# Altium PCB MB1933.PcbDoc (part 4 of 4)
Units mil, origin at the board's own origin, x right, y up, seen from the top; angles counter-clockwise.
Board outline 2755.91 x 3937.01 mil, 4 copper layers (Top Layer, GND, POWER, Bottom Layer), stack 60.63 mil thick; 228 components, 185 nets, 918 pads, 786 vias.
Unrouted connection lines stored in the file: 160.
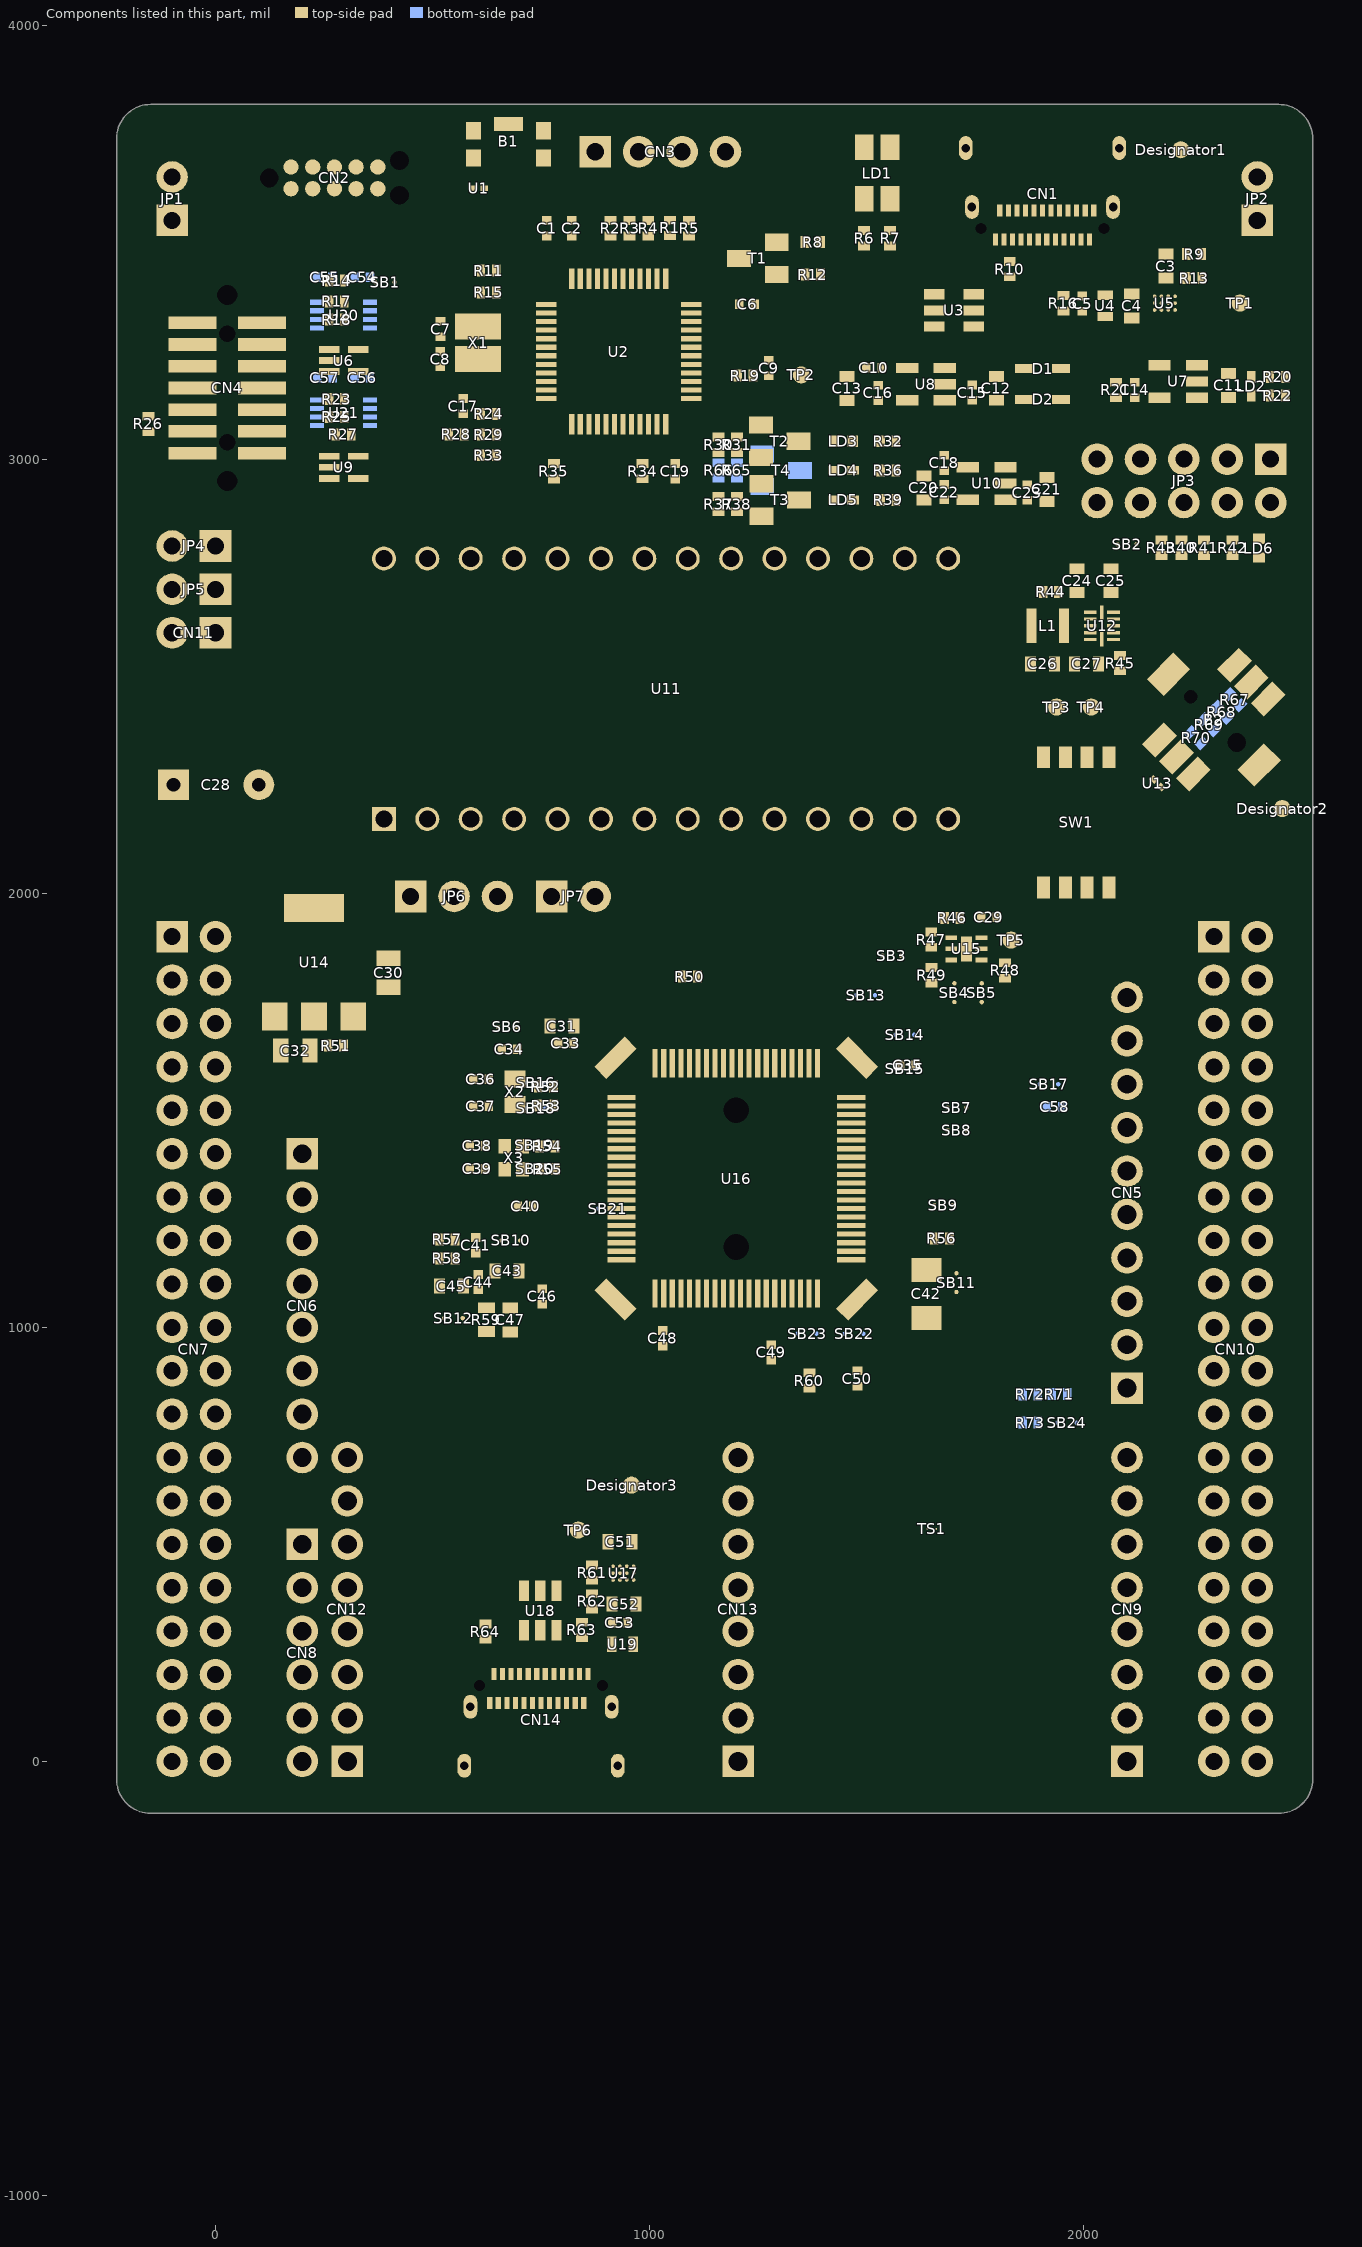
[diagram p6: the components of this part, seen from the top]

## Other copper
Top Layer:
  pour cut-out: 792.82,1551.81 ccw(c808.57,1551.81) 808.57,1536.06 ccw(c808.57,1551.81) 824.32,1551.81 ccw(c808.57,1551.81) 808.57,1567.56 ccw(c808.57,1551.81)
  region net 3V3: 1838,2694.28 1821.28,2711 1818,2711 1816,2709 1816,2673 1837.28,2694.28
  region net AVDD: 711,1057 680,1057 678,1055 687.79,1045.21 707.99,1045.21 710.78,1048
  pour cut-out: 779,3245 744.97,3245 659.97,3160 508.05,3160 485,3183.05 485,3339 504,3358 674,3358 741,3291 797,3291 797,3312 750,3312 684,3378 486,3378 464,3356 464,3160 486,3138 665.91,3138 742.91,3215 796,3215 797,3216 797,3245
  pour cut-out: 716.57,1618.17 625.41,1618.17 613.29,1630.29 621,1638 710.98,1638 716.57,1632.41
  region net VBUS2: 793.01,217.04 793.01,226.01 812.08,245.08 875.79,245.08 901.77,271.06 901.57,368.41 924.7,368.41 926.57,366.54 926.48,254.43 896.75,224.7 812.7,224.7 798.93,210.93
  region net 5V_USB: 927.46,443.68 927.46,467.03 947.05,486.61 947.05,507.68 965.26,507.68 972.05,500.89 972.05,478.94 951.77,458.66 951.77,451.67 948.13,448.03
  region net 5V_USB: 931.59,434.84 945.08,448.33 931.59,448.33
  region net VBUS2: 946,434.04 951.77,428.27 951.77,400 923.77,372 901.28,372 901.28,384.28 930,413 930,416 933,416 946,429
  region net VBUS2: 947.52,432.52 933,418 947.52,418
  region net GND: 1717.47,3196.82 1717.47,3181.75 1720.96,3178.25 1764.61,3178.25 1771.44,3185.09 1771.44,3193.47
  pour cut-out: 584.06,1549.03 584.06,1468.05 533.65,1468.05 533.65,1551.27
  pour cut-out: 559.36,1459.94 562.02,1459.94 562.02,1436.36 534.16,1436.36 534.16,1461.06
  pour cut-out: 561.03,1472.97 817.33,1472.97 817.33,1459.49 505.48,1459.49 505.48,1472.58
  pour cut-out: 538.69,1351.12 538.69,1287.34 543.02,1283.01 562.01,1283.01 565.7,1286.69 565.7,1354.62 561.52,1358.8 543.26,1358.8 541.54,1357.08
  region net VDD_MCU: 902.68,1503.97 892.73,1503.97 876.88,1519.82 876.88,1536.34 897.53,1515.69 903.53,1515.69 905.96,1513.25 905.96,1507.25
  region net VBUS: 1954.49,3495.33 1965.95,3483.87 1965.95,3435.27 2015.66,3385.57 2015.66,3379.66 1995.87,3379.66 1954.49,3421.05
  pour cut-out: 251.09,3522.13 251.09,3416.13 192.63,3416.13 188.1,3420.66
  pour cut-out: 289.13,3456.04 183.13,3456.04 183.13,3514.51 187.65,3519.03
  pour cut-out: 370.28,3494.92 339.77,3494.92 328.85,3505.84 328.85,3517.66 346.07,3534.88 347.35,3533.6 369.79,3533.6
  region net GND: 2110.2,3387.07 2137.17,3387.07 2144.95,3379.3 2144.95,3368.18 2117.19,3368.18 2109.91,3375.46 2109.91,3386.58
  region net GND: 2163.55,3375.25 2163.55,3343.76 2142.4,3343.76 2133.57,3352.58 2133.57,3375.25
  pour cut-out: 1926.42,3196.1 1926.42,3147.97 1933.61,3140.79 1937.74,3144.92 1997.59,3144.92 2006.44,3153.78 2006.44,3191.77 2003.98,3194.23
  pour cut-out: 1856.7,2453.48 1825.6,2453.48 1816.54,2462.54 1816.54,2508.31 1824.52,2516.28 1859.95,2516.28 1873.04,2502.89 1873.04,2459.19 1867.82,2453.97
  pour cut-out: 1944.69,2577.4 1894.2,2577.4 1888.39,2583.21 1890.56,2585.37 1890.56,2695.9 1848.43,2695.9 1830.55,2678.02 1830.55,2586.13 1846.27,2570.41 1868.71,2570.41
  pour cut-out: 901.08,1542.17 901.08,1576.62 891.65,1586.05 869.91,1564.31 859.86,1564.31 859.86,1526.94 870.49,1516.31
  region net VDD_MCU: 1346.66,1046.1 1341.74,1041.18 1341.74,1030.16 1269.59,958.01 1269.59,950 1290.52,950 1315.76,975.23 1353.45,1012.93 1353.45,1046.1
  region net GND: 1601.68,1615 1601.68,1595.67 1521.7,1515.69 1519.79,1515.69 1513.49,1509.39 1518.9,1503.97 1540.97,1503.97 1623,1586 1623,1615
  pour cut-out: 306.6,1795.51 247.25,1795.51 236.23,1784.49 236.23,1709.68 248.43,1697.48 297.94,1697.48 316.64,1716.18 316.64,1785.47
  region net 3V3_STLK: 808.91,3199.1 815.07,3192.95 831.8,3192.95 848.43,3209.58 848.43,3232.71 842.53,3232.71
  region net 3V3_STLK: 1114.97,3355.06 1126.88,3366.97 1197.18,3366.97 1206.73,3357.42 1206.73,3355.06
  region net VDDUSB: 1477.62,1534.09 1479,1535.47 1496.66,1535.47 1562.07,1600.88 1562.07,1621.79 1586.68,1621.79 1586.68,1597.1 1513.23,1523.66 1477.62,1523.66
  region net VDD: 2064.64,2596.32 2085.82,2596.32 2091.74,2590.39 2091.74,2545.98 2096.86,2540.86 2119,2563 2119,2586.56 2101.39,2604.17 2072.49,2604.17
  region net GND: 2008.18,2604.17 1993.22,2604.17 1975.18,2586.14 1975.18,2545.25 1991.96,2545.25 1994.2,2547.49 1994.2,2590.69 1999.91,2596.4 2011.57,2596.4 2015.43,2600.25
  region net NetL1_1: 2015.43,2616 2011.51,2619.92 1990.95,2619.92 1965.87,2645 1958.34,2645 1958.34,2584.27 1986.12,2612.04 2015.47,2612.04
  region net 5V_LP: 2037.96,2705.25 2036.23,2703.52 2036.23,2660.18 2047.84,2660.18 2074.24,2686.58 2055.57,2705.25
  region net 5V_LP: 2000.7,2637.54 2032.78,2637.54 2036.23,2640.98 2036.23,2688.51 2042,2694.28 2047.84,2694.28 2047.84,2631.73 2043.12,2627.01 2000.7,2627.01
  region net 3V3_STLK: 810.24,3508.4 810.24,3445.71 818.22,3437.73 825.01,3437.83 825.01,3513.13 823.85,3514.28 816.12,3514.28
  region net 3V3_STLK: 1038,3059.19 1046.56,3050.63 1046.56,3008.7 1055.42,2999.84 1087.61,2999.84 1091.3,3003.53 1097.55,2997.28 1097.55,2989.97 1089.05,2989.97 1050.53,2989.97 1038,3002.5 1038,3009.09
  region net VBUS: 2008.93,3385.99 2049.93,3385.99 2056.94,3378.99 2050.75,3372.8 2007.29,3372.8 2007.03,3384.1
  region net VBUS: 2198.1,3372.51 2176.84,3372.51 2174.97,3374.38 2174.97,3414.23 2179.99,3419.26 2197.61,3419.26 2199.48,3417.23 2199.48,3373.89
  region net VBUS_STLK: 2199.38,3343.76 2199.38,3327.72 2185.11,3313.45 2106.86,3313.45 2105.18,3315.13 2105.18,3327.43 2109.42,3331.66 2173.59,3331.66 2174.97,3333.04 2174.97,3343.76
  region net VREF: 851.88,1259.78 849.96,1257.86 859.85,1247.97 916.74,1247.97 920.28,1251.51 920.28,1258.01 918.51,1259.78
  region net AVDD: 908.18,1240.1 878.06,1240.1 869,1231.04 871.66,1228.38 900.6,1228.38 922.74,1228.38 927.17,1232.81 927.17,1237.54 925.2,1239.51
  region net VBAT: 925.08,1494.35 923.43,1496 887.9,1496 869.11,1514.79 858.24,1503.91 877.86,1484.29 922.94,1484.29 925.22,1486.56
  text "1" at 2213.62,2024.16 h98.43
  text ".Layer_Name" at -323.18,-712.6 h118.11
  text ".GTL" at 1318.35,-712.6 h118.11
GND:
  pour cut-out: 981.6,1420.61 981.68,1420.53 981.68,1416.18 974.38,1416.18 973,1417.56 974.28,1418.84 974.92,1418.84
  pour cut-out: 779,3245 744.97,3245 659.97,3160 508.05,3160 485,3183.05 485,3339 504,3358 674,3358 741,3291 797,3291 797,3312 750,3312 684,3378 486,3378 464,3356 464,3160 486,3138 665.91,3138 742.91,3215 796,3215 797,3216 797,3245
  pour cut-out: 968.12,1416.7 968.12,1384.78 962.31,1378.97 863.69,1378.97 794.4,1309.68 774.91,1309.68 774.91,1296.2 801.58,1296.2 867.26,1361.87 971.57,1361.87 981.68,1371.99 981.68,1416.18 979.02,1418.84 970.82,1418.84
  pour cut-out: 547.94,1309.68 774.91,1309.68 774.91,1296.2 547.94,1296.2
  pour cut-out: 584.95,1614.21 558.18,1614.21 538.2,1594.23 548.63,1583.8 560.64,1583.8 592.82,1615.98 594.3,1615.98
  pour cut-out: 562.11,1459.87 562.11,1296.1 533.47,1296.1 533.47,1459.87
  pour cut-out: 793.56,1593.18 787.4,1599.35 741.94,1599.35 713.1,1628.19 778.01,1628.19 778.55,1627.65 797.5,1627.65 797.5,1597.12
  pour cut-out: 803.85,1473.36 821.37,1455.83 821.37,1430.05 833.86,1417.56 978.55,1417.56 981.6,1420.61 981.6,1469.62 972.23,1479 890.93,1479 843.62,1526.31 843.62,1581.52 797.5,1627.65 778.55,1627.65 778.55,1604.76 817.71,1565.61 817.7,1522.1 878.39,1461.42 963.71,1461.42 969.2,1455.93 969.2,1427.01 967.51,1425.31 834.77,1425.31 831.3,1428.79 831.3,1463.43 821.37,1473.36
  pour cut-out: 561.23,1594.23 561.23,1473.46 533.77,1473.46 533.77,1594.23
  pour cut-out: 558.47,1627.65 790.36,1627.65 790.36,1614.16 558.47,1614.16
  pour cut-out: 561.03,1473.36 817.33,1473.36 817.33,1459.87 533.47,1459.87 533.47,1473.16
  text "2" at 2282.51,2024.16 h98.43
  text "M1 Layer" at -322.41,-712.78 h118.11
  text ".G1" at 1319.12,-712.78 h118.11
POWER:
  pour cut-out: 679.25,3225.3 ccw(c695,3225.3) 695,3209.56 ccw(c695,3225.3) 710.75,3225.3 ccw(c695,3225.3) 695,3241.05 ccw(c695,3225.3)
  pour cut-out: 607.59,3174.74 ccw(c623.33,3174.74) 623.33,3158.99 ccw(c623.33,3174.74) 639.08,3174.74 ccw(c623.33,3174.74) 623.33,3190.49 ccw(c623.33,3174.74)
  pour cut-out: 498.63,3175.17 ccw(c514.38,3175.17) 514.38,3159.42 ccw(c514.38,3175.17) 530.13,3175.17 ccw(c514.38,3175.17) 514.38,3190.91 ccw(c514.38,3175.17)
  pour cut-out: 482,3248.76 ccw(c497.74,3248.76) 497.74,3233.01 ccw(c497.74,3248.76) 513.49,3248.76 ccw(c497.74,3248.76) 497.74,3264.51 ccw(c497.74,3248.76)
  pour cut-out: 482.29,3282.03 ccw(c498.04,3282.03) 498.04,3266.28 ccw(c498.04,3282.03) 513.79,3282.03 ccw(c498.04,3282.03) 498.04,3297.77 ccw(c498.04,3282.03)
  pour cut-out: 676.19,3321 ccw(c691.94,3321) 691.94,3305.25 ccw(c691.94,3321) 707.68,3321 ccw(c691.94,3321) 691.94,3336.75 ccw(c691.94,3321)
  pour cut-out: 501.25,3347.13 ccw(c517,3347.13) 517,3331.38 ccw(c517,3347.13) 532.75,3347.13 ccw(c517,3347.13) 517,3362.87 ccw(c517,3347.13)
  pour cut-out: 792.82,1551.81 ccw(c808.57,1551.81) 808.57,1536.06 ccw(c808.57,1551.81) 824.32,1551.81 ccw(c808.57,1551.81) 808.57,1567.56 ccw(c808.57,1551.81)
  pour cut-out: 821.27,1372.18 ccw(c837.02,1372.18) 837.02,1356.44 ccw(c837.02,1372.18) 852.76,1372.18 ccw(c837.02,1372.18) 837.02,1387.93 ccw(c837.02,1372.18)
  pour cut-out: 736.82,1320.41 ccw(c752.57,1320.41) 752.57,1304.66 ccw(c752.57,1320.41) 768.31,1320.41 ccw(c752.57,1320.41) 752.57,1336.16 ccw(c752.57,1320.41)
  pour cut-out: 585.24,1320.9 ccw(c600.99,1320.9) 600.99,1305.16 ccw(c600.99,1320.9) 616.74,1320.9 ccw(c600.99,1320.9) 600.99,1336.65 ccw(c600.99,1320.9)
  pour cut-out: 570.09,1395.51 ccw(c585.83,1395.51) 585.83,1379.76 ccw(c585.83,1395.51) 601.58,1395.51 ccw(c585.83,1395.51) 585.83,1411.26 ccw(c585.83,1395.51)
  pour cut-out: 572.74,1448.56 ccw(c588.49,1448.56) 588.49,1432.81 ccw(c588.49,1448.56) 604.24,1448.56 ccw(c588.49,1448.56) 588.49,1464.31 ccw(c588.49,1448.56)
  pour cut-out: 794.3,1434.68 ccw(c810.05,1434.68) 810.05,1418.94 ccw(c810.05,1434.68) 825.79,1434.68 ccw(c810.05,1434.68) 810.05,1450.43 ccw(c810.05,1434.68)
  pour cut-out: 725.7,1453.68 ccw(c741.44,1453.68) 741.44,1437.93 ccw(c741.44,1453.68) 757.19,1453.68 ccw(c741.44,1453.68) 741.44,1469.43 ccw(c741.44,1453.68)
  pour cut-out: 787.41,1479.97 ccw(c803.16,1479.97) 803.16,1464.22 ccw(c803.16,1479.97) 818.9,1479.97 ccw(c803.16,1479.97) 803.16,1495.71 ccw(c803.16,1479.97)
  pour cut-out: 630.91,1480.55 ccw(c646.66,1480.55) 646.66,1464.8 ccw(c646.66,1480.55) 662.41,1480.55 ccw(c646.66,1480.55) 646.66,1496.3 ccw(c646.66,1480.55)
  pour cut-out: 577.57,1538.23 ccw(c593.31,1538.23) 593.31,1522.48 ccw(c593.31,1538.23) 609.06,1538.23 ccw(c593.31,1538.23) 593.31,1553.97 ccw(c593.31,1538.23)
  pour cut-out: 634.46,1603.78 ccw(c650.2,1603.78) 650.2,1588.03 ccw(c650.2,1603.78) 665.95,1603.78 ccw(c650.2,1603.78) 650.2,1619.53 ccw(c650.2,1603.78)
  pour cut-out: 579.44,1594.72 ccw(c595.18,1594.72) 595.18,1578.97 ccw(c595.18,1594.72) 610.93,1594.72 ccw(c595.18,1594.72) 595.18,1610.47 ccw(c595.18,1594.72)
  pour cut-out: 2178,1498 2178,1477.19 2191,1464.19 2196.81,1470 2224,1470 2224,1490 2213,1501 2205.32,1501
  pour cut-out: 521.9,536.1 521.9,356.9 515,350 432,350 432,464.31 421,475.31 478.9,533.21 478.9,540
  text "3" at 2400.62,2024.16 h98.43
  text "M2 Layer" at -322.24,-712.99 h118.11
  text ".G2" at 1319.29,-712.99 h118.11
Bottom Layer:
  pour cut-out: 679.25,3225.3 ccw(c695,3225.3) 695,3209.56 ccw(c695,3225.3) 710.75,3225.3 ccw(c695,3225.3) 695,3241.05 ccw(c695,3225.3)
  pour cut-out: 607.59,3174.74 ccw(c623.33,3174.74) 623.33,3158.99 ccw(c623.33,3174.74) 639.08,3174.74 ccw(c623.33,3174.74) 623.33,3190.49 ccw(c623.33,3174.74)
  pour cut-out: 498.63,3175.17 ccw(c514.38,3175.17) 514.38,3159.42 ccw(c514.38,3175.17) 530.13,3175.17 ccw(c514.38,3175.17) 514.38,3190.91 ccw(c514.38,3175.17)
  pour cut-out: 482,3248.76 ccw(c497.74,3248.76) 497.74,3233.01 ccw(c497.74,3248.76) 513.49,3248.76 ccw(c497.74,3248.76) 497.74,3264.51 ccw(c497.74,3248.76)
  pour cut-out: 482.29,3282.03 ccw(c498.04,3282.03) 498.04,3266.28 ccw(c498.04,3282.03) 513.79,3282.03 ccw(c498.04,3282.03) 498.04,3297.77 ccw(c498.04,3282.03)
  pour cut-out: 676.19,3321 ccw(c691.94,3321) 691.94,3305.25 ccw(c691.94,3321) 707.68,3321 ccw(c691.94,3321) 691.94,3336.75 ccw(c691.94,3321)
  pour cut-out: 501.25,3347.13 ccw(c517,3347.13) 517,3331.38 ccw(c517,3347.13) 532.75,3347.13 ccw(c517,3347.13) 517,3362.87 ccw(c517,3347.13)
  pour cut-out: 579.44,1594.72 ccw(c595.18,1594.72) 595.18,1578.97 ccw(c595.18,1594.72) 610.93,1594.72 ccw(c595.18,1594.72) 595.18,1610.47 ccw(c595.18,1594.72)
  pour cut-out: 634.46,1603.78 ccw(c650.2,1603.78) 650.2,1588.03 ccw(c650.2,1603.78) 665.95,1603.78 ccw(c650.2,1603.78) 650.2,1619.53 ccw(c650.2,1603.78)
  pour cut-out: 577.57,1538.23 ccw(c593.31,1538.23) 593.31,1522.48 ccw(c593.31,1538.23) 609.06,1538.23 ccw(c593.31,1538.23) 593.31,1553.97 ccw(c593.31,1538.23)
  pour cut-out: 630.91,1480.55 ccw(c646.66,1480.55) 646.66,1464.8 ccw(c646.66,1480.55) 662.41,1480.55 ccw(c646.66,1480.55) 646.66,1496.3 ccw(c646.66,1480.55)
  pour cut-out: 787.41,1479.97 ccw(c803.16,1479.97) 803.16,1464.22 ccw(c803.16,1479.97) 818.9,1479.97 ccw(c803.16,1479.97) 803.16,1495.71 ccw(c803.16,1479.97)
  pour cut-out: 725.7,1453.68 ccw(c741.44,1453.68) 741.44,1437.93 ccw(c741.44,1453.68) 757.19,1453.68 ccw(c741.44,1453.68) 741.44,1469.43 ccw(c741.44,1453.68)
  pour cut-out: 794.3,1434.68 ccw(c810.05,1434.68) 810.05,1418.94 ccw(c810.05,1434.68) 825.79,1434.68 ccw(c810.05,1434.68) 810.05,1450.43 ccw(c810.05,1434.68)
  pour cut-out: 572.74,1448.56 ccw(c588.49,1448.56) 588.49,1432.81 ccw(c588.49,1448.56) 604.24,1448.56 ccw(c588.49,1448.56) 588.49,1464.31 ccw(c588.49,1448.56)
  pour cut-out: 570.09,1395.51 ccw(c585.83,1395.51) 585.83,1379.76 ccw(c585.83,1395.51) 601.58,1395.51 ccw(c585.83,1395.51) 585.83,1411.26 ccw(c585.83,1395.51)
  pour cut-out: 585.24,1320.9 ccw(c600.99,1320.9) 600.99,1305.16 ccw(c600.99,1320.9) 616.74,1320.9 ccw(c600.99,1320.9) 600.99,1336.65 ccw(c600.99,1320.9)
  pour cut-out: 736.82,1320.41 ccw(c752.57,1320.41) 752.57,1304.66 ccw(c752.57,1320.41) 768.31,1320.41 ccw(c752.57,1320.41) 752.57,1336.16 ccw(c752.57,1320.41)
  pour cut-out: 821.27,1372.18 ccw(c837.02,1372.18) 837.02,1356.44 ccw(c837.02,1372.18) 852.76,1372.18 ccw(c837.02,1372.18) 837.02,1387.93 ccw(c837.02,1372.18)
  pour cut-out: 792.82,1551.81 ccw(c808.57,1551.81) 808.57,1536.06 ccw(c808.57,1551.81) 824.32,1551.81 ccw(c808.57,1551.81) 808.57,1567.56 ccw(c808.57,1551.81)
  pour cut-out: 2147.4,800 2183.1,800 2196,812.9 2177.05,831.85 2141.85,831.85 2139,829
  pour cut-out: 1111.43,2136.31 1103,2127.88 1103,2098.06 1125.06,2076 1287,2076 1287,2112.82 1293,2118.82 1275.51,2136.31
  text "4" at 2479.36,2024.16 h98.43
  text ".GBL" at 877.28,-713.86 h118.11
  text ".Layer_Name" at 2503.81,-713.86 h118.11
Multi-Layer:
  pour cut-out: 2184.09,2110.78 2184.09,1992.67 2518.73,1992.67 2518.73,2110.78
  pour cut-out: 51.57,2851.18 -151.57,2851.18 -151.57,2548.82 51.57,2548.82
  pour cut-out: 1981,3050 1981,2850 2481,2850 2481,3050
  pour cut-out: 351.36,760.04 256.46,760.04 256.42,760 256.48,759.94 256.48,-60.04 351.38,-60.04 351.42,-60 351.36,-59.94
  pour cut-out: 1251.32,756.97 1156.41,756.97 1156.43,-60 1251.33,-60
  pour cut-out: 152.5,560 247.4,560 247.44,560.04 247.44,-60.04 152.56,-60.04 152.5,-59.98
  pour cut-out: 247.5,640 247.47,639.96 152.56,639.96 152.56,1459.94 152.5,1460 247.5,1460
  pour cut-out: 2146.66,1817.95 2054.65,1817.95 2052.56,1820.04 2052.5,1819.98 2052.5,800 2147.4,800 2147.44,799.96 2147.44,1820.04
  pour cut-out: 2147.44,760.04 2052.56,760.04 2052.56,-60.04 2147.44,-60.04 2147.44,759.95 2147.5,760
  pour cut-out: 2254.93,1948.66 2256.26,1949.99 2450.01,1949.99 2450.01,-50.01 2250.01,-50.01 2250.01,1949.99
  pour cut-out: -145.07,1948.66 -143.74,1949.99 50.01,1949.99 50.01,-50.01 -149.99,-50.01 -149.99,1949.99
  pour cut-out: 823.39,3759.44 824.56,3758.26 1224.96,3758.26 1224.96,3658.65 1226.53,3657.07 823.39,3657.07
  pour cut-out: 2346.06,3703.94 2453.94,3703.94 2453.94,3496.06 2346.06,3496.06
  pour cut-out: -153.94,3703.94 -46.06,3703.94 -46.06,3496.06 -153.94,3496.06

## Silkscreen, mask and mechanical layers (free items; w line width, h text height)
Top Overlay:
  circle w5: c1035.02,1875.98 r8
  circle w5: c932.58,1878.32 r55.9
  circle w5: c822.02,1877.98 r8
  lines w5: -151.44,2521.74 ccw(c-104.35,2569.43) -56.66,2522.33 ; -150.46,2523.95 cw(c-102.77,2476.86) -55.68,2524.55 ; -53.95,2522.81 ccw(c-6.85,2570.49) 40.84,2523.4 ; -52.96,2525.02 cw(c-5.27,2477.93) 41.82,2525.61 ; 247.4,560 419,560 521,560 521,361 ; 250.06,642.12 267.88,642.12 508.88,642.12 521,642.12 521,767 521,772 ; 255.32,1140 381,1140 381,1010 ; 337.03,50 362.03,50 ; 337.03,153.54 362.03,153.54 ; 337.03,247.36 362.03,247.36 ; 337.03,348.52 362.03,348.52 ; 337.03,449.5 362.03,449.5 ; 337.03,550 362.03,550 ; 337.03,645.81 362.03,645.81 ; 400,-59 521,-59 521,188 521,240 ; 1138.94,50 1163.94,50 ; 1138.94,150 1163.94,150 ; 1138.94,250 1163.94,250 ; 1138.94,350 1163.94,350 ; 1138.94,450 1163.94,450 ; 1138.94,550 1163.94,550 ; 1138.94,650 1163.94,650
  lines w5.98: 822.02,1877.98 876.02,1877.98 ; 987.92,1875.98 1035.02,1875.98
  lines w7.87: 2092.92,2759.94 2308.34,2759.94 ; 2309.83,2759.94 2308.34,2759.94 ; 2376.16,2848.27 2376.16,2759.94 2308.34,2759.94
  text "RESERVED" at 859.92,3762.19 h70
  text "COM" at 1456.8,3762.19 h70
  text "TAG10" at -75.05,3757.26 h70
  text "STLINK" at 2149.81,3591.47 h70 r90
  text "RESET" at 539.31,3542 h70
  text "MCO" at 1296.96,3231.44 h70
  text "5V_" at 1979.1,3105.35 h47.24
  text "STLK" at 2389.87,3062.64 h47.24
  text "E5V" at 2296.86,3062.05 h47.24
  text "USB" at 2184.65,3059.39 h47.24
  text "CHG" at 1979.69,3058.27 h47.24
  text "VIN" at 2096.02,3058.27 h47.24
  text "DEBUG_IN" at -135.84,2863.31 h70
  text "5V SOURCE" at 1971.27,2833.4 h47.24 r90
  text "STLK_RST" at 78,2790 h60
  text "NRST" at 90.16,2677.74 h60
  text "UP" at 2266.76,2604 h70
  text "Battery" at 90.16,2575 h70
  text "-" at -111.62,2502.8 h70
  text "+" at -18.51,2498.57 h70
  text "+" at -190.28,2225.76 h70
  text "Segment LCD" at 298.97,2166.77 h70 r90
  text "JOYSTICK" at 2112.83,2116.22 h65
  text "IDD" at 935.61,1969.92 h70
  text "VDD" at 381.94,1888.09 h70
  text "VDD_MCU" at 553.61,1886.36 h70
  text "PD5" at 84.92,1878.09 h47.24 r90
  text "PD4" at -158.27,1868.31 h47.24 r90
  text "PD3" at 2244.54,1864.6 h47.24 r90
  text "PA10" at 2486.52,1862.89 h47.24 r90
  text "A" at 903.58,1850 h100
  text "J" at 1095.48,1844.49 h600
  text "PC8" at 2499.22,1770 h47.24 r90
  text "PC11" at 87.31,1765.69 h47.24 r90
  text "PC9" at 2230.72,1763.03 h47.24 r90
  text "PC10" at -172.45,1761.75 h47.24 r90
  text "D15" at 1935.01,1740 h70
  text "PB8" at 2244.54,1669.14 h47.24 r90
  text "E5V" at 88.29,1667.33 h47.24 r90
  text "PB9" at -158.27,1666.41 h47.24 r90
  text "PC6" at 2486.52,1666.63 h47.24 r90
  text "D14" at 1935.53,1660 h70
  text "PB7" at 2230.72,1576.51 h47.24 r90
  text "PC5" at 2499.22,1569.14 h47.24 r90
  text "PD12" at 99,1556.93 h47.24 r90
  text "VREF" at 1871.77,1540 h70
  text "VDDUSB" at -191.85,1532.2 h47.24 r90
  text "VREF" at 2486.52,1456.07 h47.24 r90
  text "PD13" at 88.26,1450 h47.24 r90
  text "AVDD" at 2244.98,1450 h47.24 r90
  text "AGND" at 1871.7,1440 h70
  text "PF3-BT0" at -158.27,1438.72 h47.24 r90
  text "PE7" at 122.22,1368.22 h47.24 r90
  text "PD8" at 2498.89,1363.62 h47.24 r90
  text "PD6" at -172.45,1353.19 h47.24 r90
  text "AGND" at 2210,1345.95 h47.24 r90
  text "D13" at 1935.34,1340 h70
  text "IOREF" at 260,1280 h70
  text "PA5" at 2241.73,1268 h47.24 r90
  text "PD9" at -156.78,1262.34 h47.24 r90
  text "PA12" at 2486.52,1260 h47.24 r90
  text "D12" at 1935.79,1240 h70
  text "VDDMCU" at 88.29,1208.67 h47.24 r90
  text "NRST" at 260,1180 h70
  text "PA6" at 2230.72,1164.19 h47.24 r90
  text "PA11" at 2498.89,1163.12 h47.24 r90
  text "PA13" at -176.76,1159.98 h47.24 r90
  text "NRST" at 123.08,1150.14 h47.24 r90
  text "D11" at 1944.02,1140 h70
  text "3V3" at 260,1080 h70
  text "PA7" at 2244.98,1069.14 h47.24 r90
  text "VDD" at 97,1064.21 h47.24 r90
  text "PA14" at -159.54,1060.5 h47.24 r90
  text "PB12" at 2486.52,1060.65 h47.24 r90
  text "D10" at 1935.47,1040 h70
  text "5V" at 260,980 h70
  text "5V" at 87.31,976.9 h47.24 r90
  text "PA8" at -176.6,963.55 h47.24 r90
  text "PB11" at 2498.89,962.5 h47.24 r90
  text "PA15" at 2230.72,960 h47.24 r90
  text "D9" at 1970.13,940 h70
  text "GND" at 260,880 h70
  text "PC7" at 2244.54,867.33 h47.24 r90
  text "GND" at 2486.52,864.25 h47.24 r90
  text "PD0" at -158.27,863.62 h47.24 r90
  text "GND" at 96.56,860.67 h47.24 r90
  text "D8" at 1970.13,840 h70
  text "VREFBUF" at 558.78,800 h47.24 r90
  text "GND" at 260,780 h70
  text "POWER" at 449.96,778.25 h70 r90
  text "PB2" at 2498.89,767.91 h47.24 r90
  text "PA9" at -173.73,766.09 h47.24 r90
  text "PB6" at 2229.47,763.41 h47.24 r90
  text "GND" at 87.31,760.01 h47.24 r90
  text "VIN" at 400,682 h70
  text "D7" at 1970.13,679.38 h70
  text "PD2" at 2241.73,665 h47.24 r90
  text "PB1" at 2486.52,665 h47.24 r90
  text "PE8" at 96.56,662.5 h47.24 r90
  text "PC13" at -156.78,659.49 h47.24 r90
  text "GND" at 1148.94,660 h47.24 r90
  text "MB1933C" at 1340,658 h98.43
  text "GND" at 392.03,655.81 h47.24 r90
  text "K" at 1722,653 h400
  text "D6" at 1969.24,574 h70
  text "R" at 602.95,572.07 h400
  text "PE9" at 87.31,566.09 h47.24 r90
  text "5V" at 392.03,565.81 h47.24 r90
  text "PB15" at 2498.89,565.3 h47.24 r90
  text "3V3" at 1148.94,560 h47.24 r90
  text "PB10" at 2227.77,559.15 h47.24 r90
  text "PC14" at -173.73,552.78 h47.24 r90
  text "D5" at 1968.82,472 h70
  text "A0" at 410,471 h70
  text "PB4" at 2241.73,465.73 h47.24 r90
  text "PB14" at 2486.52,462.5 h47.24 r90
  text "PA0" at 96.56,460.52 h47.24 r90
  text "MOSI" at 1120.16,457.06 h47.24 r90
  text "SDA" at 392.03,455.81 h47.24 r90
  text "PC15" at -158.27,449 h47.24 r90
  text "A1" at 410,371 h70
  text "D4" at 1969.24,370 h70
  text "PA1" at 88.29,368.41 h47.24 r90
  text "PF0" at -173.79,365 h47.24 r90
  text "PB5" at 2227.96,365 h47.24 r90
  text "SCL" at 392.03,355.81 h47.24 r90
  text "PB13" at 2498.89,355.93 h47.24 r90
  text "MISO" at 1148.94,355 h47.24 r90
  text "D3" at 1968.82,271.26 h70
  text "A2" at 410,271 h70
  text "TX" at 391.32,269.68 h47.24 r90
  text "PB3" at 2241.73,268.23 h47.24 r90
  text "PD1" at 2486.52,268.23 h47.24 r90
  text "PF1" at -158.27,264.51 h47.24 r90
  text "PA4" at 96.26,261.41 h47.24 r90
  text "SCK" at 1148.94,260 h47.24 r90
  text "AIN" at 536.96,253.25 h70 r90
  text "D2" at 1968.82,174.67 h70
  text "RX" at 391.32,172.56 h47.24 r90
  text "A3" at 410,171 h70
  text "PC4" at 2499.22,170.66 h47.24 r90
  text "CS" at 1148.94,170 h47.24 r90
  text "PB0" at 88.29,167.7 h47.24 r90
  text "VBAT" at -173.73,158.33 h47.24 r90
  text "PC12" at 2227.11,157.33 h47.24 r90
  text "INT" at 392.03,76.34 h47.24 r90
  text "D1" at 1970.13,73.07 h70
  text "A4" at 410,71 h70
  text "PC2" at -158.27,65 h47.24 r90
  text "PC1" at 96.89,65 h47.24 r90
  text "PA2" at 2241.73,65 h47.24 r90
  text "RST" at 1148.94,60 h47.24 r90
  text "PD11" at 2486.52,59.86 h47.24 r90
  text "A5" at 410,-14.04 h70
  text "D0" at 1970.13,-20 h70
  text "PC3" at -173.82,-31.84 h47.24 r90
  text "PC0" at 88.29,-34.56 h47.24 r90
  text "PA3" at 2227.11,-34.71 h47.24 r90
  text "AN" at 1148.94,-40 h47.24 r90
  text "PD10" at 2498.89,-48.23 h47.24 r90
  text "PWM" at 392.03,-60.04 h47.24 r90
  text "USER" at 1075,-79.13 h70 r90
  text ".Layer_Name" at -323.18,-712.6 h118.11
  text ".GTO" at 1318.35,-712.6 h118.11
Bottom Overlay:
  drawing of 176 lines, arcs and shapes, not listed
  text "G" at 737.52,2897.77 h400
  text "F" at 1082,2896.2 h400
  text "S" at 1734.65,2856.14 h400
  text "C" at 625.02,1649.15 h400
  text "H" at 505.52,1392.06 h400
  text "I" at 505.13,1099.64 h400
  text "E" at 542.82,813.92 h400
  text "CN5" at 2160,760 h70
  text "CN6" at 260,580 h70
  text "CN7" at 10,-110 h70
  text "CN8" at 260,-110 h70
  text "CN9" at 2160,-110 h70
  text "CN10" at 2430,-110 h70
  text ".GBO" at 877.28,-713.86 h118.11
  text ".Layer_Name" at 2503.81,-713.86 h118.11
Top Paste:
  text ".Layer_Name" at -323.18,-712.6 h118.11
  text ".GTP" at 1318.35,-712.6 h118.11
Bottom Paste:
  text ".GBP" at 877.28,-713.86 h118.11
  text ".Layer_Name" at 2503.81,-713.86 h118.11
Top Solder:
  rectangle: 2193.93,2004.48 2508.89,2102.9
  text ".Layer_Name" at -323.18,-712.6 h118.11
  text ".GTS" at 1318.35,-712.6 h118.11
Bottom Solder:
  rectangle: 2193.93,2004.48 2508.89,2102.9
  text ".GBS" at 877.28,-713.86 h118.11
  text ".Layer_Name" at 2503.81,-713.86 h118.11
M1-Board Shape:
  lines w5: -227.95,-41.01 -227.95,2084 ; -227.95,-40.95 ccw(c-149.21,-40.95) -149.21,-119.69 ; -227.95,2085.04 -227.95,2970.87 ; -227.95,2970.8 -227.95,3738.21 ; -227.95,3738.52 cw(c-149.21,3738.52) -149.21,3817.26 2449.22,3817.26 cw(c2449.22,3738.52) 2527.96,3738.52 ; -149.21,-119.75 219.69,-119.75 224.81,-119.75 1681.5,-119.75 ; 219.69,-119.69 224.81,-119.69 ; 2527.96,-40.95 2527.96,2045.67 2527.96,2970.87 ; 2527.96,-41.01 cw(c2449.22,-41.01) 2449.22,-119.75 1681.5,-119.75 ; 2527.96,2970.81 2527.96,3738.21 ; 1681.5,-119.75 1681.5,-119.75
M2-Board Dimensions:
  text ".Layer_Name" at -323.18,-712.6 h118.11
  text ".GM2" at 1318.35,-712.6 h118.11
Drill Drawing:
  drawing of 607 lines, arcs and shapes, not listed
  text "Symbol" at -131.1,6467.46 h85.04
  text "Count" at 202.04,6467.46 h85.04
  text "Hole Size" at 547.66,6467.46 h85.04
  text "Plated" at 1161.77,6467.46 h85.04
  text "Hole Type" at 1454.22,6467.46 h85.04
  text "Drill Layer Pair" at 1879.99,6467.46 h85.04
  text "Via/Pad" at 2687.04,6467.46 h85.04
  text "Pad Shape" at 3035.92,6467.46 h85.04
  text "Template" at 3491.67,6467.46 h85.04
  text "Hole Length" at 4444.61,6467.46 h85.04
  text "Routed Path Length" at 5058.72,6467.46 h85.04
  text "1" at 202.04,6320.68 h70.87
  text "11.81mil (0.30mm)" at 547.66,6320.68 h70.87
  text "PTH" at 1161.77,6320.68 h70.87
  text "Round" at 1454.22,6320.68 h70.87
  text "Top Layer - Bottom Layer" at 1879.99,6320.68 h70.87
  text "Via" at 2687.04,6320.68 h70.87
  text "Rounded" at 3035.92,6320.68 h70.87
  text "v50h30m0mx0" at 3491.67,6320.68 h70.87
  text "-" at 4444.61,6320.68 h70.87
  text "-" at 5058.72,6320.68 h70.87
  text "1" at 202.04,6173.9 h70.87
  text "31.50mil (0.80mm)" at 547.66,6173.9 h70.87
  text "NPTH" at 1161.77,6173.9 h70.87
  text "Round" at 1454.22,6173.9 h70.87
  text "Top Layer - Bottom Layer" at 1879.99,6173.9 h70.87
  text "Pad" at 2687.04,6173.9 h70.87
  text "Rounded" at 3035.92,6173.9 h70.87
  text "c0hn80m85p-1" at 3491.67,6173.9 h70.87
  text "-" at 4444.61,6173.9 h70.87
  text "-" at 5058.72,6173.9 h70.87
  text "2" at 202.04,6027.12 h70.87
  text "25.59mil (0.65mm)" at 547.66,6027.12 h70.87
  text "NPTH" at 1161.77,6027.12 h70.87
  text "Round" at 1454.22,6027.12 h70.87
  text "Top Layer - Bottom Layer" at 1879.99,6027.12 h70.87
  text "Pad" at 2687.04,6027.12 h70.87
  text "Rounded" at 3035.92,6027.12 h70.87
  text "c0hn65m5" at 3491.67,6027.12 h70.87
  text "-" at 4444.61,6027.12 h70.87
  text "-" at 5058.72,6027.12 h70.87
  text "2" at 202.04,5880.34 h70.87
  text "25.59mil (0.65mm)" at 547.66,5880.34 h70.87
  text "NPTH" at 1161.77,5880.34 h70.87
  text "Slot" at 1454.22,5880.34 h70.87
  text "Top Layer - Bottom Layer" at 1879.99,5880.34 h70.87
  text "Pad" at 2687.04,5880.34 h70.87
  text "Rounded" at 3035.92,5880.34 h70.87
  text "c0hn65_95m5" at 3491.67,5880.34 h70.87
  text "37.40mil (0.95mm)" at 4444.61,5880.34 h70.87
  text "11.81mil (0.30mm)" at 5058.72,5880.34 h70.87
  text "2" at 202.04,5733.56 h70.87
  text "31.50mil (0.80mm)" at 547.66,5733.56 h70.87
  text "PTH" at 1161.77,5733.56 h70.87
  text "Round" at 1454.22,5733.56 h70.87
  text "Top Layer - Bottom Layer" at 1879.99,5733.56 h70.87
  text "Pad" at 2687.04,5733.56 h70.87
  text "(Mixed)" at 3035.92,5733.56 h70.87
  text "(Mixed)" at 3491.67,5733.56 h70.87
  text "-" at 4444.61,5733.56 h70.87
  text "-" at 5058.72,5733.56 h70.87
  text "2" at 202.04,5586.78 h70.87
  text "38.19mil (0.97mm)" at 547.66,5586.78 h70.87
  text "NPTH" at 1161.77,5586.78 h70.87
  text "Round" at 1454.22,5586.78 h70.87
  text "Top Layer - Bottom Layer" at 1879.99,5586.78 h70.87
  text "Pad" at 2687.04,5586.78 h70.87
  text "Rounded" at 3035.92,5586.78 h70.87
  text "c0hn97m102" at 3491.67,5586.78 h70.87
  text "-" at 4444.61,5586.78 h70.87
  text "-" at 5058.72,5586.78 h70.87
  text "2" at 202.04,5440 h70.87
  text "46.85mil (1.19mm)" at 547.66,5440 h70.87
  text "NPTH" at 1161.77,5440 h70.87
  text "Round" at 1454.22,5440 h70.87
  text "Top Layer - Bottom Layer" at 1879.99,5440 h70.87
  text "Pad" at 2687.04,5440 h70.87
  text "Rounded" at 3035.92,5440 h70.87
  text "c0hn119m124" at 3491.67,5440 h70.87
  text "-" at 4444.61,5440 h70.87
  text "-" at 5058.72,5440 h70.87
  text "2" at 202.04,5293.22 h70.87
  text "59.06mil (1.50mm)" at 547.66,5293.22 h70.87
  text "NPTH" at 1161.77,5293.22 h70.87
  text "Round" at 1454.22,5293.22 h70.87
  text "Top Layer - Bottom Layer" at 1879.99,5293.22 h70.87
  text "Pad" at 2687.04,5293.22 h70.87
  text "Rounded" at 3035.92,5293.22 h70.87
  text "c0hn150m155" at 3491.67,5293.22 h70.87
  text "-" at 4444.61,5293.22 h70.87
  text "-" at 5058.72,5293.22 h70.87
  text "4" at 202.04,5146.44 h70.87
  text "43.31mil (1.10mm)" at 547.66,5146.44 h70.87
  text "NPTH" at 1161.77,5146.44 h70.87
  text "Round" at 1454.22,5146.44 h70.87
  text "Top Layer - Bottom Layer" at 1879.99,5146.44 h70.87
  text "Pad" at 2687.04,5146.44 h70.87
  text "Rounded" at 3035.92,5146.44 h70.87
  text "(Mixed)" at 3491.67,5146.44 h70.87
  text "-" at 4444.61,5146.44 h70.87
  text "-" at 5058.72,5146.44 h70.87
  text "8" at 202.04,4999.66 h70.87
  text "19.69mil (0.50mm)" at 547.66,4999.66 h70.87
  text "PTH" at 1161.77,4999.66 h70.87
  text "Slot" at 1454.22,4999.66 h70.87
  text "Top Layer - Bottom Layer" at 1879.99,4999.66 h70.87
  text "Pad" at 2687.04,4999.66 h70.87
  text "Rounded" at 3035.92,4999.66 h70.87
  text "r140_80h50_110r100m145_85" at 3491.67,4999.66 h70.87
  text "43.31mil (1.10mm)" at 4444.61,4999.66 h70.87
  text "23.62mil (0.60mm)" at 5058.72,4999.66 h70.87
  text "45" at 202.04,4852.88 h70.87
  text "15.75mil (0.40mm)" at 547.66,4852.88 h70.87
  text "PTH" at 1161.77,4852.88 h70.87
  text "Round" at 1454.22,4852.88 h70.87
  text "Top Layer - Bottom Layer" at 1879.99,4852.88 h70.87
  text "Via" at 2687.04,4852.88 h70.87
  text "Rounded" at 3035.92,4852.88 h70.87
  text "v70h40m0mx0" at 3491.67,4852.88 h70.87
  text "-" at 4444.61,4852.88 h70.87
  text "-" at 5058.72,4852.88 h70.87
  text "48" at 202.04,4706.1 h70.87
  text "43.31mil (1.10mm)" at 547.66,4706.1 h70.87
  text "PTH" at 1161.77,4706.1 h70.87
  text "Round" at 1454.22,4706.1 h70.87
  text "Top Layer - Bottom Layer" at 1879.99,4706.1 h70.87
  text "Pad" at 2687.04,4706.1 h70.87
  text "Rounded" at 3035.92,4706.1 h70.87
  text "(Mixed)" at 3491.67,4706.1 h70.87
  text "-" at 4444.61,4706.1 h70.87
  text "-" at 5058.72,4706.1 h70.87
  text "137" at 202.04,4559.32 h70.87
  text "39.37mil (1.00mm)" at 547.66,4559.32 h70.87
  text "PTH" at 1161.77,4559.32 h70.87
  text "Round" at 1454.22,4559.32 h70.87
  text "Top Layer - Bottom Layer" at 1879.99,4559.32 h70.87
  text "Pad" at 2687.04,4559.32 h70.87
  text "Rounded" at 3035.92,4559.32 h70.87
  text "(Mixed)" at 3491.67,4559.32 h70.87
  text "-" at 4444.61,4559.32 h70.87
  text "-" at 5058.72,4559.32 h70.87
  text "740" at 202.04,4412.54 h70.87
  text "9.84mil (0.25mm)" at 547.66,4412.54 h70.87
  text "PTH" at 1161.77,4412.54 h70.87
  text "Round" at 1454.22,4412.54 h70.87
  text "Top Layer - Bottom Layer" at 1879.99,4412.54 h70.87
  text "Via" at 2687.04,4412.54 h70.87
  text "Rounded" at 3035.92,4412.54 h70.87
  text "v45h25m0mx0" at 3491.67,4412.54 h70.87
  text "-" at 4444.61,4412.54 h70.87
  text "-" at 5058.72,4412.54 h70.87
  text "996 Total" at 202.04,4265.76 h70.87
  text "Slot definitions :" at -131.1,4163.01 h70.87
  text "Routed Path Length" at 352.59,4163.01 h70.87
  text "= Calculated from tool start centre position to tool end centre position." at 951.79,4163.01 h70.87
  text "Hole Length" at 352.59,4104.3 h70.87
  text "= Routed Path Length + Tool Size = Slot length as defined in the PCB layout" at 729.34,4104.3 h70.87
  text "PCB SPECIFICATIONS :" at 3110.03,3593.71 h118.11
  text "A.   MATERIAL :" at 3110.03,3436.23 h118.11
  text "FR-4" at 4625.77,3436.23 h118.11
  text "TG-170" at 5275.38,3436.23 h118.11
  text "X  TG-150" at 5993.89,3436.23 h118.11
  text "TG-140" at 6623.81,3436.23 h118.11
  text "B.   MATERIAL FAMILY :" at 3110.03,3318.12 h118.11
  text "N/A" at 4625.77,3318.12 h118.11
  text "C.   SOLDERMASK COLOR :" at 3110.03,3200.01 h118.11
  text "GREEN" at 4625.77,3200.01 h118.11
  text "X  BLUE" at 5275.38,3200.01 h118.11
  text "RED" at 5993.89,3200.01 h118.11
  text "BLACK" at 6623.81,3200.01 h118.11
  text "D.   SILKSCREEN COLOR :" at 3110.03,3081.9 h118.11
  text "X    WHITE" at 4625.77,3081.9 h118.11
  text "YELLOW" at 5275.38,3081.9 h118.11
  text "BLACK" at 5993.89,3081.9 h118.11
  text "Blue ink PANTONE 2955" at 6623.81,3081.9 h118.11
  text "E.   SURFACE FINISH :" at 3110.03,2963.79 h118.11
  text "X  ENIG" at 4625.77,2963.79 h118.11
  text "IMMERSION SILVER" at 5275.38,2963.79 h118.11
  text "IMMERSION TIN" at 6623.81,2963.79 h118.11
  text "HASL" at 4625.77,2845.68 h118.11
  text "HASL (PB-FREE)" at 5275.38,2845.68 h118.11
  text "GOLDEN FINGER" at 6623.81,2845.68 h118.11
  text "F.   IMPEDANCE CONTROL :" at 3110.03,2727.57 h118.11
  text "NO" at 4625.77,2727.57 h118.11
  text "X  YES  (SEE IMPEDANCE TABLE FOR DETAIL INFORMATION)" at 5275.38,2727.57 h118.11
  text "G.   THROUGH VIA :" at 3110.03,2609.46 h118.11
  text "PLUG THE VIAS WHICH ARE COVERED WITH SOLDERMASK ONE OR TWO SIDE." at 4625.77,2609.46 h118.11
  text "PLUG MATERIAL :" at 4625.77,2491.35 h118.11
  text "X  SOLDERMASK" at 5629.71,2491.35 h118.11
  text "NON-CONDUCTIVE EPOXY." at 6623.81,2491.35 h118.11
  text "H.   STACK-UP :" at 3110.03,2373.24 h118.11
  text "SEE LAYER STACK-UP SEQUENCE FOR OVERALL THICKNESS." at 4625.77,2373.24 h118.11
  text "Layer" at 3152.3,2067.64 h60
  text "Name" at 3562.21,2067.64 h60
  text "Material" at 4491.96,2067.64 h60
  text "Thickness" at 5351.72,2067.64 h60
  text "Constant" at 6001.56,2067.64 h60
  text "Board Layer Stack" at 6571.42,2067.64 h60
  text "PCB : TYPE 3" at 7773.57,2024.57 h118.11
  text "Top Overlay" at 3562.21,1947.64 h60
  text "Top Solder" at 3562.21,1827.64 h60
  text "Solder Resist" at 4491.96,1827.64 h60
  text "0.015mm" at 5351.72,1827.64 h60
  text "3.5" at 6001.56,1827.64 h60
  text "ASPECT-RATIO, AXE Z :" at 7773.57,1808.04 h118.11
  text "1" at 3152.3,1707.64 h60
  text "Top Layer" at 3562.21,1707.64 h60
  text "0.035mm" at 5351.72,1707.64 h60
  text "Dielectric 1" at 3562.21,1587.64 h60
  text "FR-4" at 4491.96,1587.64 h60
  text "0.200mm" at 5351.72,1587.64 h60
  text "4.2" at 6001.56,1587.64 h60
  text "6:1 to 8:1 / LEVEL \"B\"" at 7774.3,1542.39 h118.11
  text "2" at 3152.3,1467.64 h60
  text "GND" at 3562.21,1467.64 h60
  text "0.035mm" at 5351.72,1467.64 h60
  text "Dielectric 3" at 3562.21,1347.64 h60
  text "1.000mm" at 5351.72,1347.64 h60
  text "4.2" at 6001.56,1347.64 h60
  text "MINIMUM PARAMETERS" at 7775.37,1321.88 h118.11
  text "3" at 3152.3,1227.64 h60
  text "POWER" at 3562.21,1227.64 h60
  text "0.035mm" at 5351.72,1227.64 h60
  text "Dielectric 2" at 3562.21,1107.64 h60
  text "0.200mm" at 5351.72,1107.64 h60
  text "4.2" at 6001.56,1107.64 h60
  text "DEFAULT" at 7775.37,1105.34 h118.11
  text "4" at 3152.3,987.64 h60
  text "Bottom Layer" at 3562.21,987.64 h60
  text "0.035mm" at 5351.72,987.64 h60
  text "TRACKS : 0.14mm           / GAPS : 0.127mm" at 7775.37,878.96 h118.11
  text "Bottom Solder" at 3562.21,867.64 h60
  text "Solder Resist" at 4491.96,867.64 h60
  text "0.015mm" at 5351.72,867.64 h60
  text "3.5" at 6001.56,867.64 h60
  text "Bottom Overlay" at 3562.21,747.64 h60
  text "IMPEDANCE TABLE   USB HS STLINK" at 3115.81,466.71 h118.11
  text "LAYER" at 3283.13,269.86 h118.11
  text "TRACE" at 3922.89,269.86 h118.11
  text "SPACING" at 4336.28,269.86 h118.11
  text "IMPEDANCE" at 4867.78,269.86 h118.11
  text "IMPEDANCE" at 5537.07,269.86 h118.11
  text "TOL." at 6275.26,269.86 h118.11
  text "(mm)" at 4467.18,172.42 h98.43
  text "(mm)" at 4001.63,170.45 h98.43
  text "(Single ended)" at 4887.46,161.59 h98.43
  text "(Differential)" at 5586.28,161.59 h98.43
  text "+/- 15%" at 6238.05,18.29 h118.11
  text "0.27" at 3961.28,14.94 h118.11
  text "TOP" at 3134.7,13.37 h118.11
  text "0.2" at 4434.7,13.96 h118.11
  text "n/a" at 4999.86,11.4 h118.11
  text "90 ohm" at 5633.17,4.47 h118.11
  text ".Layer_Name" at -323.18,-712.6 h118.11
  text ".DRL" at 1318.35,-712.6 h118.11
M20-Top Title Box:
  circle w10: c2747.85,-977.19 r51.18
  region: 2729.16,-692.3 2117.85,-692.3 2090.52,-762.19 2042.85,-810.42 1987.85,-737.19 1987.85,-672.19 2032.85,-617.19 2089.39,-602.3 2729.16,-602.3
  region: 2177.85,-1020.23 1754.39,-1020.23 1793.5,-922.09 2102.85,-922.09 2120.52,-892.19 2207.47,-992.52
  lines w10: 1793.5,-922.09 2139.63,-922.09 2018.92,-782.8 cw(c2089.93,-706.27) 2099.39,-602.3 2759.39,-602.3 2729.39,-692.3 ; 1923.96,-592.57 cw(c2019.47,-630.77) 2028.79,-528.32 ; 1925.5,-591.29 1754.39,-1020.23 2515.12,-1020.23 ccw(c2524.91,-912.58) 2625.27,-952.72 ; 1993.99,-746.2 2207.47,-992.52 ; 2003.99,-746.2 2212.85,-987.19 ; 2003.99,-736.2 2212.85,-977.19 ; 2007.85,-692.3 2519.39,-692.3 ; 2008.99,-731.2 2217.85,-972.19 ; 2013.99,-726.2 2222.85,-967.19 ; 2018.99,-721.2 2227.85,-962.19 ; 2023.99,-716.2 2232.85,-957.19 ; 2026.15,-639.33 2235.01,-880.32 ; 2028.84,-528.33 2794.57,-528.33 2625.31,-952.63 ; 2028.99,-711.2 2235.71,-949.72 ; 2028.99,-701.2 2237.85,-942.19 ; 2028.99,-691.2 2237.85,-932.19 ; 2028.99,-656.2 2237.85,-897.19 ; 2033.99,-686.2 2242.85,-927.19 ; 2033.99,-671.2 2242.85,-912.19 ; 2088,-922.62 ccw(c2092.13,-901.54) 2103.85,-883.55 ; 2130.77,-691.77 ccw(c2129.75,-714.11) 2116.75,-732.3 2209.85,-839.73 cw(c2138.84,-916.26) 2167.68,-1016.6 ; 2378.07,-1012.19 2491.82,-682.3 ; 2386.82,-1010.23 2499.79,-682.64 ; 2391.82,-1010.23 2504.79,-682.64 ; 2401.82,-1010.23 2514.79,-682.64 ; 2411.82,-1010.23 2524.79,-682.64 ; 2421.82,-1010.23 2534.79,-682.64 ; 2431.82,-1010.23 2544.79,-682.64 ; 2441.82,-1010.23 2554.79,-682.64 ; 2451.82,-1010.23 2564.79,-682.64 ; 2461.82,-1010.23 2574.79,-682.64 ; 2470.04,-1012.19 2583.79,-682.3 ; 2583.79,-692.3 2729.16,-692.3 ; 2702.85,-692.19 2732.85,-602.19 ; 2709.39,-692.3 2739.39,-602.3 ; 2719.39,-692.3 2749.39,-602.3
  lines w11.81: -677.52,-976.38 1684.69,-976.38 ; -677.52,-779.53 1684.69,-779.53 ; -677.52,-582.68 1684.69,-582.68 ; 897.29,-1173.23 897.29,-582.68 ; 1684.69,-1173.23 1684.69,-385.83 ; 2378.07,-1012.19 2470.04,-1012.19 ; -677.5,-1173.23 -677.5,-385.83 2865.79,-385.83 2865.79,-1173.23 -677.52,-1173.23
  text "Project: '.Board_Name'" at -638.14,-512.44 h118.11
  text "Layer:" at -638.13,-712.6 h118.11
  text "Gerber:" at 936.22,-712.6 h118.11
  text "Variant: '.VariantName'" at -638.14,-909.45 h118.11
  text "Ref: '.Board_Reference'" at 941.22,-909.45 h118.11
  text "R" at 2727.85,-1007.19 h60
  text "Date: '.Board_Document_Date'" at -638.14,-1106.3 h118.11
  text "Rev: '.Board_PCB_Revision'" at 938.98,-1106.3 h118.11
M21-Bottom Title Box:
  circle w10: c-552.21,-977.19 r51.18
  region: 17.79,-1020.23 441.26,-1020.23 402.15,-922.09 92.79,-922.09 75.13,-892.19 -11.83,-992.52
  region: -533.51,-692.3 77.79,-692.3 105.13,-762.19 152.79,-810.42 207.79,-737.19 207.79,-672.19 162.79,-617.19 106.26,-602.3 -533.51,-602.3
  lines w10: -553.74,-602.3 -523.74,-692.3 ; -543.74,-602.3 -513.74,-692.3 ; -537.21,-602.19 -507.21,-692.19 ; -533.74,-692.3 -563.74,-602.3 96.26,-602.3 cw(c105.71,-706.27) 176.73,-782.8 56.01,-922.09 402.15,-922.09 ; -533.51,-692.3 -388.15,-692.3 ; -429.66,-952.63 -598.93,-528.33 166.81,-528.33 ; -429.63,-952.72 ccw(c-329.26,-912.58) -319.47,-1020.23 441.26,-1020.23 270.15,-591.29 ; -388.15,-682.3 -274.39,-1012.19 ; -379.14,-682.64 -266.18,-1010.23 ; -369.14,-682.64 -256.18,-1010.23 ; -359.14,-682.64 -246.18,-1010.23 ; -349.14,-682.64 -236.18,-1010.23 ; -339.14,-682.64 -226.18,-1010.23 ; -329.14,-682.64 -216.18,-1010.23 ; -323.74,-692.3 187.79,-692.3 ; -319.14,-682.64 -206.18,-1010.23 ; -309.14,-682.64 -196.18,-1010.23 ; -304.14,-682.64 -191.18,-1010.23 ; -296.18,-682.3 -182.42,-1012.19 ; -47.21,-927.19 161.65,-686.2 ; -47.21,-912.19 161.65,-671.2 ; -42.21,-942.19 166.65,-701.2 ; -42.21,-932.19 166.65,-691.2 ; -42.21,-897.19 166.65,-656.2 ; -40.06,-949.72 166.65,-711.2 ; -39.36,-880.32 169.5,-639.33 ; -37.21,-957.19 171.65,-716.2 ; -32.21,-962.19 176.65,-721.2 ; -27.21,-967.19 181.65,-726.2 ; -22.21,-972.19 186.65,-731.2 ; -17.21,-987.19 191.65,-746.2 ; -17.21,-977.19 191.65,-736.2 ; -11.83,-992.52 201.65,-746.2 ; 27.96,-1016.6 cw(c56.81,-916.26) -14.21,-839.73 78.9,-732.3 ccw(c65.89,-714.11) 64.87,-691.77 ; 91.79,-883.55 ccw(c103.51,-901.54) 107.65,-922.62 ; 166.86,-528.32 cw(c176.17,-630.77) 271.69,-592.57
  lines w11.81: -274.39,-1012.19 -182.42,-1012.19 ; 503.59,-1173.23 503.59,-385.83 ; 503.59,-976.38 2865.79,-976.38 ; 503.59,-779.53 2865.79,-779.53 ; 503.59,-582.68 2865.79,-582.68 ; 1290.99,-1173.23 1290.99,-582.68 ; -677.52,-1173.23 2865.79,-1173.23 2865.79,-385.83 -677.52,-385.83 -677.52,-1173.23
  text "Project: '.Board_Name'" at 2818.78,-512.44 h118.11
  text "Gerber:" at 1244.42,-712.6 h118.11
  text "Layer:" at 2818.77,-712.6 h118.11
  text "Ref: '.Board_Reference'" at 1244.42,-909.45 h118.11
  text "Variant: '.VariantName'" at 2818.78,-909.45 h118.11
  text "R" at -532.21,-1007.19 h60
  text "Rev: '.Board_PCB_Revision'" at 1246.67,-1106.3 h118.11
  text "Date: '.Board_Document_Date'" at 2818.78,-1106.3 h118.11

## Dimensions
300,0 to 1200,0 on M2-Board Dimensions
200,0 to -227.95,-41.01 on M2-Board Dimensions
-227.95,3738.21 to 2527.96,3738.21 on M2-Board Dimensions
-100,0 to 2300,0 on M2-Board Dimensions
-149.21,3817.26 to 224.81,-119.75 on M2-Board Dimensions
199.23,55.93 to 2099.23,55.93 on M2-Board Dimensions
